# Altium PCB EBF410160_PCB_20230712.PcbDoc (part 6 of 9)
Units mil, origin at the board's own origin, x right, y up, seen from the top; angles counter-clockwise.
Board outline 5393.69 x 3858.26 mil, 6 copper layers (TOP, GND02, ART03, POW04, GND05, BOTTOM), stack 47.2 mil thick; 572 components, 434 nets, 2057 pads, 1177 vias.
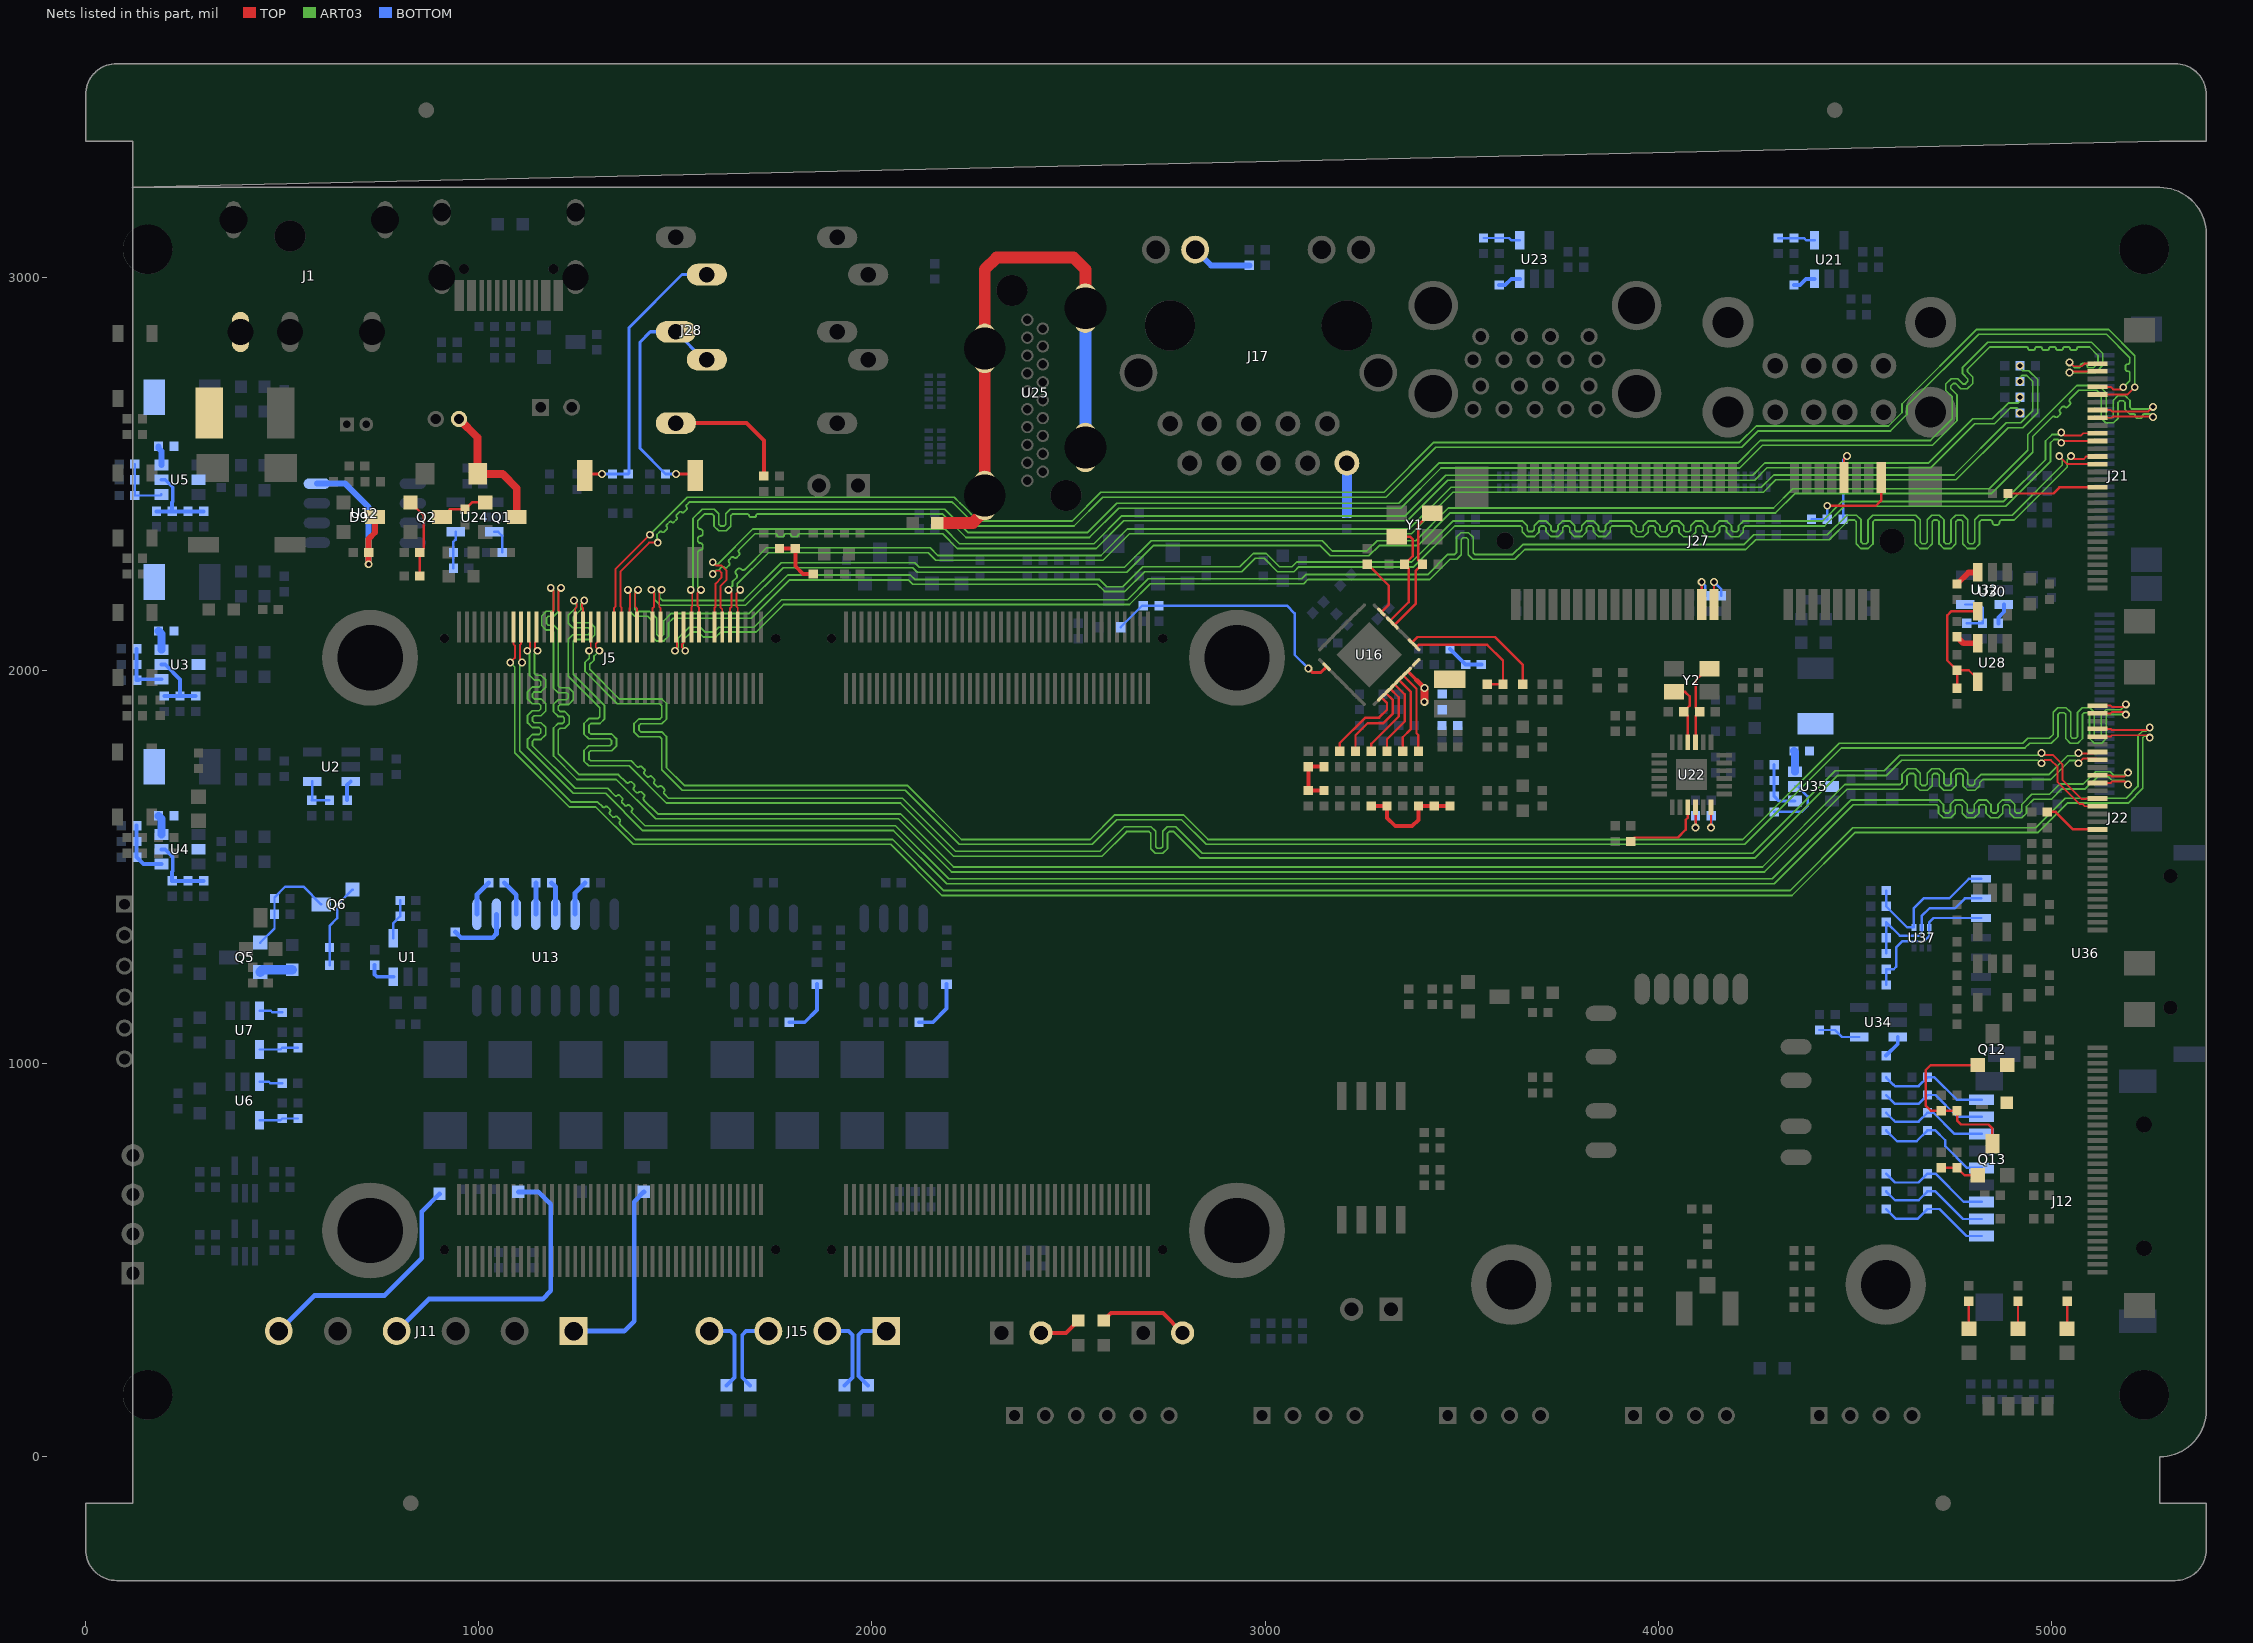
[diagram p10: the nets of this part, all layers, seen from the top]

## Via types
v1: diameter 20, hole 12, TOP to BOTTOM, 1177 vias

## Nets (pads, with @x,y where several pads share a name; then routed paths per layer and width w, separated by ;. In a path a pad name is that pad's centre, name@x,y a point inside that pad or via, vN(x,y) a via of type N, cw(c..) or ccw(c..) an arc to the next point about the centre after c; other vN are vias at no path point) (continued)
MIPI_CSI_RX_D2N: J5.69 R178.1 R180.1 | length 3734.7
  TOP w4.88: v1(1595,2275) 1603.56,2266.44 1617.58,2266.44 1630,2254.02 1630,2230.46 1615,2215.46 1615,2160 1619.28,2155.72 J5.69@1619.28,2110.98
  ART03 w4.44: v1(1595,2275) 1599.85,2270.16 1606.28,2270.15 1607.46,2270.15 1697.31,2360 2185,2360 2222.56,2322.44 2564.85,2322.44 2635.4,2392.99 3356.06,2392.99 3459.43,2496.36 4240.1,2496.36 4271.53,2527.79 4687.79,2527.79 4800,2640 4850,2640 4890,2680 4915,2680 4920,2685 v1(4920,2695)
MIPI_CSI_RX_D2P: J5.67 R176.1 R177.1 | length 3753
  TOP w4.88: v1(1595,2245) 1603.56,2253.56 1612.24,2253.56 1617.12,2248.68 1617.12,2235.79 1602.12,2220.79 1602.12,2162.12 1599.6,2159.6 J5.67@1599.6,2110.98
  ART03 w4.44: v1(1595,2245) 1595,2246.44 1603.56,2255 1609.9,2255 1617.09,2262.18 cw(c1620.64,2258.63) 1624.19,2262.18 ccw(c1627.75,2265.74) 1631.3,2262.18 1636.75,2267.63 ccw(c1633.2,2271.19) 1636.75,2274.74 cw(c1640.31,2278.3) 1636.75,2281.85 1642.2,2287.3 cw(c1645.76,2283.75) 1649.31,2287.3 ccw(c1652.87,2290.85) 1656.42,2287.3 1661.87,2292.75 ccw(c1658.32,2296.3) 1661.87,2299.86 cw(c1665.42,2303.41) 1661.87,2306.97 1702.46,2347.56 1754.84,2347.56 cw(c1754.84,2343.78) 1758.62,2343.78 ccw(c1762.4,2343.78) 1762.4,2340 1772.6,2340 ccw(c1772.6,2343.78) 1776.38,2343.78 cw(c1780.16,2343.78) 1780.16,2347.56 1790.36,2347.56 cw(c1790.36,2343.78) 1794.14,2343.78 ccw(c1797.92,2343.78) 1797.92,2340 1808.12,2340 ccw(c1808.12,2343.78) 1811.9,2343.78 cw(c1815.68,2343.78) 1815.68,2347.56 2179.85,2347.56 2217.41,2310 2570,2310 2640.55,2380.55 3361.21,2380.55 3464.58,2483.92 4245.25,2483.92 4276.68,2515.35 4692.94,2515.35 4805.15,2627.56 4855.15,2627.56 4895.15,2667.56 4912.44,2667.56 4920,2660 v1(4920,2655)
MIPI_CSI_RX_D3N: J5.73 R184.1 R185.1 | length 3768.8
  TOP w4.88: J5.73@1658.65,2110.98 1658.65,2159.1 1655.71,2162.04 1655.71,2195.71 v1(1665,2205)
  ART03 w4.44: v1(1665,2205) 1657.44,2212.56 1657.44,2220 1736.88,2299.44 2142.97,2299.44 2162.41,2280 2587.59,2280 2655.15,2347.56 3372.2,2347.56 3478.01,2453.37 4267.57,2453.37 4298.88,2484.68 4757.27,2484.68 4890.15,2617.56 4927.56,2617.56 4965,2655 4965,2740 4942.56,2762.44 4927,2762.44 4920,2769.44 v1(4920,2775)
MIPI_CSI_RX_D3P: J5.71 R182.1 R183.1 | length 3768.6
  TOP w4.88: v1(1635,2205) 1642.83,2197.17 1642.83,2162.13 1638.97,2158.27 J5.71@1638.97,2110.98
  ART03 w4.44: v1(1635,2205) 1645,2215 1645,2225.15 1654.88,2235.03 ccw(c1649.92,2239.99) 1654.88,2244.95 cw(c1659.84,2249.91) 1654.88,2254.87 1657.51,2257.51 cw(c1662.47,2252.55) 1667.44,2257.51 ccw(c1672.4,2262.47) 1677.36,2257.51 1731.73,2311.88 2148.12,2311.88 2167.56,2292.44 2582.44,2292.44 2650,2360 3367.05,2360 3472.86,2465.81 4262.42,2465.81 4293.73,2497.12 4752.12,2497.12 4885,2630 4922.41,2630 4952.56,2660.15 4952.56,2734.85 4937.41,2750 4925,2750 4920,2745 v1(4920,2735)
MIPI_DSI_TX0_CLKN: J5.53 J21.24 | length 4491.4
  TOP w4.88: J5.53@1461.8,2110.98 1461.8,2159.1 1458.86,2162.04 1458.86,2198.95 v1(1464.96,2205.05) ; J21.24@5117.47,2662.33 5150.54,2662.33 5153.95,2658.92 5246.74,2658.92 5250.74,2662.92 5250.82,2662.92 v1(5258.38,2670.48)
  ART03 w4.44: v1(1464.96,2205.05) 1459.96,2200.04 1459.96,2184.44 1466.3,2178.1 1673.1,2178.1 1768.8,2273.8 2108.8,2273.8 2120.15,2262.44 2642.44,2262.44 2710,2330 3145,2330 3171.22,2303.78 3258.78,2303.78 3285,2330 3382.91,2330 3466.03,2413.12 4293.12,2413.12 4342.26,2462.26 4842.26,2462.26 4940,2560 4940,2600 5064.85,2724.85 5120.15,2724.85 5139.36,2705.64 5139.36,2646.88 5143.81,2642.44 5152.69,2642.44 5157.12,2646.88 5157.12,2686.7 5168.85,2698.43 5188.04,2698.43 5199.77,2686.7 5199.77,2669.12 5204.2,2664.68 5252.58,2664.68 v1(5258.38,2670.48)
MIPI_DSI_TX0_CLKP: J5.51 J21.23 | length 4544.6
  TOP w4.88: v1(1438.96,2205.05) 1445.98,2198.02 1445.98,2162.13 1442.12,2158.27 J5.51@1442.12,2110.98 ; J21.23@5117.47,2642.64 5153.81,2642.64 5157.22,2646.04 5256.82,2646.04 v1(5258.38,2644.48)
  ART03 w4.44: v1(1438.96,2205.05) 1447.52,2196.49 1447.52,2179.29 1461.14,2165.66 1678.25,2165.66 1773.95,2261.36 2103.64,2261.36 2115,2250 2647.59,2250 2715.15,2317.56 3139.85,2317.56 3166.07,2291.34 3263.93,2291.34 3290.15,2317.56 3388.06,2317.56 3471.18,2400.68 4298.27,2400.68 4347.41,2449.82 4847.41,2449.82 4952.44,2554.85 4952.44,2594.85 5002.7,2645.1 cw(c5006.02,2641.78) 5009.35,2645.1 ccw(c5012.68,2648.43) 5016,2645.1 5021.91,2651.01 ccw(c5018.58,2654.34) 5021.91,2657.66 cw(c5025.23,2660.99) 5021.91,2664.31 5027.81,2670.22 cw(c5031.14,2666.89) 5034.47,2670.22 ccw(c5037.79,2673.55) 5041.12,2670.22 5047.03,2676.13 ccw(c5043.7,2679.45) 5047.03,2682.78 ; 5047.02,2682.78 cw(c5050.35,2686.11) 5047.02,2689.43 5070,2712.41 5115,2712.41 5126.93,2700.48 5126.93,2641.73 5138.65,2630 5157.84,2630 5169.56,2641.73 5169.56,2681.55 5174.01,2685.99 5182.89,2685.99 5187.32,2681.55 5187.32,2663.97 5199.05,2652.24 5208.49,2652.24 cw(c5208.49,2646.92) 5213.81,2646.92 ccw(c5219.13,2646.92) 5219.13,2641.6 5226.25,2641.6 ccw(c5226.25,2646.92) 5231.57,2646.92 cw(c5236.89,2646.92) 5236.89,2652.24 5250.62,2652.24 v1(5258.38,2644.48)
MIPI_DSI_TX0_D0N: J5.43 J21.27 | length 4526.5
  TOP w4.88: J5.43@1363.38,2110.98 1363.38,2159.1 1360.44,2162.04 1360.44,2252.22 1433.22,2325 v1(1455,2325) ; J21.27@5117.47,2721.38 5150.55,2721.38 5156.93,2715 5177.56,2715 v1(5182.7,2720.14)
  ART03 w4.44: v1(1455,2325) 1453.22,2326.78 1453.22,2345.63 1459.9,2352.3 cw(c1462.79,2349.42) 1465.68,2352.31 ccw(c1468.57,2355.19) 1471.45,2352.31 1478.24,2359.09 ccw(c1475.35,2361.97) 1478.23,2364.86 cw(c1481.12,2367.75) 1478.23,2370.64 1485.02,2377.42 cw(c1487.9,2374.53) 1490.79,2377.42 ccw(c1493.68,2380.31) 1496.57,2377.42 1503.35,2384.2 ccw(c1500.46,2387.09) 1503.35,2389.98 cw(c1506.24,2392.87) 1503.35,2395.76 1510.13,2402.54 cw(c1513.02,2399.65) 1515.91,2402.54 ccw(c1518.8,2405.43) 1521.69,2402.54 1528.47,2409.32 ccw(c1525.58,2412.21) 1528.47,2415.1 cw(c1531.36,2417.99) 1528.47,2420.88 1535.69,2428.1 2204.31,2428.1 2211.59,2420.82 2265,2367.41 2513.8,2367.41 2587.05,2440.66 3307.44,2440.66 3434.29,2567.51 4212.51,2567.51 4254.15,2609.15 4590.79,2609.15 4632.44,2650.8 4632.44,2672.44 4815,2855 5140,2855 5199.5,2795.5 5199.5,2784.51 cw(c5193.9,2784.51) 5193.9,2778.92 ccw(c5193.9,2773.32) 5188.31,2773.32 5188.31,2766.75 ccw(c5193.9,2766.75) 5193.9,2761.16 cw(c5193.9,2755.56) 5199.5,2755.56 5199.5,2736.94 v1(5182.7,2720.14)
MIPI_DSI_TX0_D0P: J5.41 J21.26 | length 4538.3
  TOP w4.88: J5.41@1343.69,2110.98 1343.69,2158.27 1347.56,2162.13 1347.56,2257.56 v1(1435,2345) ; J21.26@5117.47,2701.7 5193.36,2701.7 v1(5211.94,2720.28)
  ART03 w4.44: v1(1435,2345) 1530.54,2440.54 2209.46,2440.54 2224.03,2425.97 2227.68,2422.32 2270.15,2379.85 2508.65,2379.85 2581.9,2453.1 3302.29,2453.1 3429.14,2579.95 4207.36,2579.95 4249,2621.59 4585.64,2621.59 4620,2655.95 4620,2677.59 4809.85,2867.44 5145.15,2867.44 5211.94,2800.65 v1(5211.94,2720.28)
MIPI_DSI_TX0_D1N: J5.47 J21.21 | length 4560.8
  TOP w4.88: J5.47@1402.75,2110.98 1402.75,2157.25 1397.88,2162.12 1397.88,2197.88 v1(1405,2205) ; v1(5025,2605) 5032.33,2597.67 5075.52,2597.67 5081.12,2603.27 J21.21@5117.47,2603.27
  ART03 w4.44: v1(1405,2205) 1397.44,2197.44 1397.44,2154.44 1401.88,2150 1435,2150 1452.26,2132.74 1452.26,2091.88 1456.7,2087.44 1465.58,2087.44 1470.02,2091.88 1470.02,2125.71 1489.31,2145 1687.84,2145 1785.52,2242.68 2097.32,2242.68 2108.55,2231.45 2578.55,2231.45 2596.9,2213.1 2638.1,2213.1 2688.46,2263.46 2935.87,2263.46 2969.84,2297.43 3002.57,2297.43 3036.54,2263.46 3068.46,2263.46 3080.68,2275.68 3373.05,2275.68 3477.16,2379.79 3654.88,2379.79 3666.61,2368.06 3666.61,2357.54 3671.05,2353.1 3679.93,2353.1 3684.37,2357.54 3684.37,2368.06 3696.09,2379.79 3715.28,2379.79 3727.01,2368.06 3727.01,2357.54 3731.45,2353.1 3740.33,2353.1 3744.77,2357.54 3744.77,2368.06 3756.49,2379.79 3775.68,2379.79 3787.41,2368.06 3787.41,2357.54 3791.85,2353.1 3800.73,2353.1 3805.17,2357.54 3805.17,2368.06 3816.89,2379.79 3836.08,2379.79 3847.81,2368.06 3847.81,2357.54 3852.25,2353.1 3861.13,2353.1 3865.57,2357.54 3865.57,2368.06 3877.29,2379.79 3932.37,2379.79 3944.1,2368.06 3944.1,2356.88 3948.54,2352.44 3957.42,2352.44 3961.86,2356.88 3961.86,2368.06 3973.59,2379.79 3992.77,2379.79 4004.5,2368.06 4004.5,2356.88 4008.94,2352.44 4017.82,2352.44 4022.26,2356.88 4022.26,2368.06 4033.99,2379.79 4053.17,2379.79 4064.9,2368.06 4064.9,2356.88 4069.34,2352.44 4078.22,2352.44 4082.66,2356.88 4082.66,2368.06 4094.39,2379.79 4113.57,2379.79 4125.3,2368.06 4125.3,2356.88 4129.74,2352.44 4138.62,2352.44 4143.06,2356.88 4143.06,2368.06 4154.79,2379.79 4174.53,2379.79 4186.26,2368.06 4186.26,2356.88 4190.7,2352.44 4199.58,2352.44 4204.02,2356.88 4204.02,2368.06 4215.75,2379.79 4417.74,2379.79 4467.81,2429.86 4878.67,2429.86 4985,2536.19 4985,2583.47 5001.41,2599.88 5019.88,2599.88 v1(5025,2605)
MIPI_DSI_TX0_D1P: J5.45 J21.20 | length 4577
  TOP w4.88: v1(1379,2205) 1385,2199 1385,2160 1383.06,2158.07 J5.45@1383.06,2110.98 ; v1(5025,2579) 5029.59,2583.59 J21.20@5117.47,2583.59
  ART03 w4.44: v1(1379,2205) 1385,2199 1385,2149.29 1396.73,2137.56 1429.85,2137.56 1439.82,2127.59 1439.82,2086.73 1451.55,2075 1470.73,2075 1482.46,2086.73 1482.46,2120.56 1494.46,2132.56 1692.99,2132.56 1790.67,2230.24 2092.17,2230.24 2103.4,2219.01 2573.4,2219.01 2591.75,2200.66 2643.25,2200.66 2693.61,2251.02 2941.02,2251.02 2974.99,2284.99 2997.42,2284.99 3031.39,2251.02 3073.61,2251.02 3085.83,2263.24 3378.2,2263.24 3482.31,2367.35 3649.73,2367.35 3654.17,2362.91 3654.17,2352.39 3665.89,2340.66 3685.08,2340.66 3696.81,2352.39 3696.81,2362.91 3701.25,2367.35 3710.13,2367.35 3714.57,2362.91 3714.57,2352.39 3726.29,2340.66 3745.48,2340.66 3757.21,2352.39 3757.21,2362.91 3761.65,2367.35 3770.53,2367.35 3774.97,2362.91 3774.97,2352.39 3786.69,2340.66 3805.88,2340.66 3817.61,2352.39 3817.61,2362.91 3822.05,2367.35 3830.93,2367.35 3835.37,2362.91 3835.37,2352.39 3847.09,2340.66 3866.28,2340.66 3878.01,2352.39 3878.01,2362.91 3882.45,2367.35 3927.22,2367.35 3931.66,2362.91 3931.66,2351.73 3943.39,2340 3962.57,2340 3974.3,2351.73 3974.3,2362.91 3978.74,2367.35 3987.62,2367.35 3992.06,2362.91 3992.06,2351.73 4003.79,2340 4022.97,2340 4034.7,2351.73 4034.7,2362.91 4039.14,2367.35 4048.02,2367.35 4052.46,2362.91 4052.46,2351.73 4064.19,2340 4083.37,2340 4095.1,2351.73 4095.1,2362.91 4099.54,2367.35 4108.42,2367.35 4112.86,2362.91 4112.86,2351.73 4124.59,2340 4143.77,2340 4155.5,2351.73 4155.5,2362.91 4159.94,2367.35 4169.38,2367.35 4173.82,2362.91 4173.82,2351.73 4185.55,2340 4204.73,2340 4216.46,2351.73 4216.46,2362.91 4220.9,2367.35 4422.89,2367.35 4472.96,2417.42 4883.82,2417.42 4997.44,2531.04 4997.44,2578.31 5006.57,2587.44 5016.56,2587.44 v1(5025,2579)
MIPI_DSI_TX0_D2N: J5.59 J21.18 | length 4523.9
  TOP w4.88: J5.59@1520.86,2110.98 1520.86,2070.86 1516.99,2067 1516.99,2058.01 v1(1525,2050) ; v1(5050,2545) 5057.59,2537.41 5082.41,2537.41 5089.22,2544.22 J21.18@5117.47,2544.22
  ART03 w4.44: v1(1525,2050) 1520,2055 1520,2077.41 1540.15,2097.56 1558.19,2097.56 1570.75,2085 1602.59,2085 1615.15,2097.56 1705.15,2097.56 1775.15,2167.56 2655.15,2167.56 2708.25,2220.66 3098.25,2220.66 3108.81,2231.22 3418.81,2231.22 3470.15,2282.56 3487.26,2282.56 3498.99,2294.29 3498.99,2333.12 3503.43,2337.56 3512.31,2337.56 3516.75,2333.12 3516.75,2294.29 3528.48,2282.56 3635.15,2282.56 3660.15,2307.56 4222.56,2307.56 4247.56,2332.56 4435.15,2332.56 4485.15,2382.56 4499.02,2382.56 4503.46,2378.12 4503.46,2321.73 4515.19,2310 4534.37,2310 4546.1,2321.73 4546.1,2378.12 4550.54,2382.56 4649.51,2382.56 4653.95,2378.12 4653.95,2321.73 4665.68,2310 4684.86,2310 4696.59,2321.73 4696.59,2378.12 4701.03,2382.56 4709.91,2382.56 4714.35,2378.12 4714.35,2321.73 4726.08,2310 4745.27,2310 4756.99,2321.73 4756.99,2378.12 4761.43,2382.56 4770.31,2382.56 4774.75,2378.12 4774.75,2321.73 4786.48,2310 4805.66,2310 4817.39,2321.73 4817.39,2378.12 4821.83,2382.56 4843.95,2382.56 cw(c4843.95,2376.28) 4850.23,2376.28 ccw(c4856.51,2376.28) 4856.51,2370 4861.71,2370 ccw(c4861.71,2376.28) 4867.99,2376.28 cw(c4874.27,2376.28) 4874.27,2382.56 4905.15,2382.56 5040,2517.41 5040,2536.01 5048.99,2545 v1(5050,2545)
MIPI_DSI_TX0_D2P: J5.57 J21.17 | length 4540.7
  TOP w4.88: v1(1499,2050) 1499.23,2050 1504.12,2054.88 1504.12,2070.89 1501.17,2073.83 J5.57@1501.17,2110.98 ; v1(5020,2545) 5040.47,2524.53 J21.17@5117.47,2524.53
  ART03 w4.44: v1(1499,2050) 1499.23,2050 1507.56,2058.33 1507.56,2082.56 1535,2110 1563.34,2110 1575.9,2097.44 1597.44,2097.44 1610,2110 1700,2110 1770,2180 2650,2180 2703.1,2233.1 3093.1,2233.1 3103.66,2243.66 3413.66,2243.66 3465,2295 3482.11,2295 3486.55,2299.44 3486.55,2338.27 3498.28,2350 3517.46,2350 3529.19,2338.27 3529.19,2299.44 3533.63,2295 3630,2295 3655,2320 4217.41,2320 4242.41,2345 4430,2345 4480,2395 4504.17,2395 4515.9,2383.27 4515.9,2326.88 4520.34,2322.44 4529.22,2322.44 4533.66,2326.88 4533.66,2383.27 4545.39,2395 4654.66,2395 4666.39,2383.27 4666.39,2326.88 4670.83,2322.44 4679.71,2322.44 4684.15,2326.88 4684.15,2383.27 4695.88,2395 4715.06,2395 4726.79,2383.27 4726.79,2326.88 4731.23,2322.44 4740.11,2322.44 4744.55,2326.88 4744.55,2383.27 4756.28,2395 4775.47,2395 4787.19,2383.27 4787.19,2326.88 4791.63,2322.44 4800.51,2322.44 4804.95,2326.88 4804.95,2383.27 4816.68,2395 4900,2395 5027.56,2522.56 5027.56,2537.44 v1(5020,2545)
MIPI_DSI_TX0_D3N: J5.63 J21.30 | length 4537.1
  TOP w4.88: J5.63@1560.23,2110.98 1560.23,2159.77 1555.78,2164.22 1555.78,2195.78 v1(1565,2205) ; v1(5046.24,2783.6) 5056.21,2773.62 5077.57,2773.62 5084.39,2780.44 J21.30@5117.47,2780.44
  ART03 w4.44: v1(1565,2205) 1557.05,2212.95 1557.05,2299.59 cw(c1563.6,2299.59) 1563.6,2306.13 ccw(c1563.6,2311.97) 1569.43,2311.97 1569.43,2318.06 ccw(c1563.6,2318.06) 1563.6,2323.89 cw(c1563.6,2330.44) 1557.05,2330.44 1557.05,2335.11 cw(c1563.6,2335.11) 1563.6,2341.65 ccw(c1563.6,2347.49) 1569.43,2347.49 1569.43,2353.58 ccw(c1563.6,2353.58) 1563.6,2359.41 cw(c1563.6,2365.96) 1557.05,2365.96 1557.05,2381.17 1573.44,2397.56 1593.63,2397.56 1598.07,2393.12 1598.07,2366.73 1609.8,2355 1628.98,2355 1640.71,2366.73 1640.71,2393.12 1645.15,2397.56 1683.71,2397.56 cw(c1683.71,2393.78) 1687.49,2393.78 ccw(c1691.27,2393.78) 1691.27,2390 1701.47,2390 ccw(c1701.47,2393.78) 1705.25,2393.78 cw(c1709.03,2393.78) 1709.03,2397.56 2179.85,2397.56 2239.31,2338.1 2553.1,2338.1 2627.56,2412.56 3345.02,2412.56 3447.29,2514.83 4207.42,2514.83 4265.24,2572.65 4697.65,2572.65 4759.96,2634.96 4759.96,2701 4743.79,2717.16 4743.79,2723.44 4750.08,2729.72 4756.36,2729.72 4769.76,2716.32 4786.34,2716.32 4799.91,2729.89 4799.91,2746.47 4786.51,2759.88 4786.51,2766.15 4842.91,2822.56 4936.9,2822.56 cw(c4936.9,2818.78) 4940.68,2818.78 ccw(c4944.46,2818.78) 4944.46,2815 4954.66,2815 ccw(c4954.66,2818.78) 4958.44,2818.78 cw(c4962.22,2818.78) 4962.22,2822.56 4972.42,2822.56 cw(c4972.42,2818.78) 4976.2,2818.78 ccw(c4979.98,2818.78) 4979.98,2815 4990.18,2815 ccw(c4990.18,2818.78) 4993.96,2818.78 cw(c4997.74,2818.78) 4997.74,2822.56 5007.94,2822.56 cw(c5007.94,2818.78) 5011.72,2818.78 ccw(c5015.5,2818.78) 5015.5,2815 5025.7,2815 ccw(c5025.7,2818.78) 5029.48,2818.78 cw(c5033.26,2818.78) 5033.26,2822.56 5043.46,2822.56 cw(c5043.46,2818.78) 5047.24,2818.78 ccw(c5051.02,2818.78) 5051.02,2815 5061.22,2815 ccw(c5061.22,2818.78) 5065,2818.78 cw(c5068.78,2818.78) 5068.78,2822.56 5096.78,2822.56 5118.24,2801.1 5118.24,2781.29 5106.99,2770.04 5095.05,2770.04 cw(c5095.05,2774.06) 5091.02,2774.06 ; v1(5046.24,2783.6) 5059.8,2770.04 5069.24,2770.04 ccw(c5069.24,2774.06) 5073.26,2774.06 ; 5073.26,2774.08 cw(c5079.63,2774.08) 5079.63,2780.45 5084.66,2780.45 cw(c5084.66,2774.08) 5091.02,2774.08
MIPI_DSI_TX0_D3P: J5.61 J21.29 | length 4500.3
  TOP w4.88: v1(1539,2205) 1542.9,2201.1 1542.9,2162.9 1540.54,2160.54 J5.61@1540.54,2110.98 ; v1(5046.24,2757.6) 5049.38,2760.74 J21.29@5117.47,2760.74
  ART03 w4.44: v1(1539,2205) 1544.61,2210.61 1544.61,2386.32 1568.29,2410 1598.79,2410 1610.51,2398.27 1610.51,2371.88 1614.95,2367.44 1623.83,2367.44 1628.27,2371.88 1628.27,2398.27 1640,2410 2185,2410 2244.46,2350.54 2547.95,2350.54 2622.41,2425 3339.87,2425 3442.14,2527.27 4202.27,2527.27 4260.09,2585.09 4692.5,2585.09 4747.52,2640.11 4747.52,2695.84 4731.35,2712.01 4731.35,2728.59 4744.93,2742.16 4761.51,2742.16 4774.91,2728.76 4781.19,2728.76 4787.47,2735.04 4787.47,2741.32 4774.07,2754.72 4774.07,2771.31 4837.76,2835 5101.93,2835 5130.68,2806.25 5130.68,2776.14 5112.14,2757.6 v1(5046.24,2757.6)
MIPI_DSI_TX1_CLKN: J5.27 J22.24 | length 5042.5
  TOP w4.88: J5.27@1205.9,2110.98 1205.9,2149.1 1202.88,2152.12 1202.88,2203.87 v1(1209.06,2210.05) ; v1(5069,1790) 5070.02,1788.98 5114.13,1788.98 J22.24@5117.47,1792.33
  ART03 w4.44: v1(1209.06,2210.05) 1202.28,2203.26 1202.28,2149.47 1190.55,2137.74 1176.88,2137.74 1172.44,2133.3 1172.44,2119.43 1176.88,2114.99 1190.55,2114.99 1202.28,2103.26 1202.28,1960.26 1206.72,1955.82 1228.27,1955.82 1240,1944.09 1240,1924.91 1228.27,1913.18 1206.72,1913.18 1202.28,1908.74 1202.28,1899.86 1206.72,1895.42 1218.27,1895.42 1230,1883.69 1230,1864.51 1218.27,1852.78 1206.72,1852.78 1202.28,1848.34 1202.28,1787.72 1255,1735 1355,1735 1374.73,1715.27 ccw(c1378.48,1719.02) 1382.23,1715.27 cw(c1385.98,1711.52) 1389.73,1715.27 1394.79,1710.21 cw(c1391.04,1706.46) 1394.79,1702.71 ccw(c1398.54,1698.96) 1394.79,1695.21 1399.85,1690.15 ccw(c1403.6,1693.9) 1407.35,1690.15 cw(c1411.1,1686.4) 1414.85,1690.15 1419.91,1685.09 cw(c1416.16,1681.34) 1419.91,1677.59 ccw(c1423.66,1673.84) 1419.91,1670.09 1455,1635 2072.59,1635 2207.59,1500 4265,1500 4475,1710 4615,1710 4620,1715 4620,1736.13 4633.87,1750 4654.75,1750 4666.47,1738.27 4666.47,1711.88 4670.91,1707.44 4679.79,1707.44 4684.23,1711.88 4684.23,1738.27 4695.96,1750 4715.15,1750 4726.87,1738.27 4726.87,1711.88 4731.31,1707.44 4740.19,1707.44 4744.63,1711.88 4744.63,1738.27 4756.36,1750 4775.55,1750 4787.27,1738.27 4787.27,1711.88 4791.71,1707.44 4800.59,1707.44 4805.03,1711.88 4805.03,1720.03 4820,1735 4992.94,1735 5040.94,1783 5062,1783 v1(5069,1790)
MIPI_DSI_TX1_CLKP: J5.25 J22.23 | length 5044
  TOP w4.88: v1(1183.06,2210.05) 1190,2203.1 1190,2151.78 1186.21,2148 J5.25@1186.21,2110.98 ; v1(5069,1764) 5069.08,1764 5081.18,1776.11 5114,1776.11 J22.23@5117.47,1772.64
  ART03 w4.44: v1(1183.06,2210.05) 1189.84,2203.26 1189.84,2154.62 1185.4,2150.18 1171.73,2150.18 1160,2138.46 1160,2114.27 1171.73,2102.55 1185.4,2102.55 1189.84,2098.11 1189.84,1955.11 1201.56,1943.38 1223.12,1943.38 1227.56,1938.94 1227.56,1930.06 1223.12,1925.62 1201.56,1925.62 1189.84,1913.89 1189.84,1894.71 1201.56,1882.98 1213.12,1882.98 1217.56,1878.54 1217.56,1869.66 1213.12,1865.22 1201.56,1865.22 1189.84,1853.49 1189.84,1782.57 1249.85,1722.56 1349.85,1722.56 1449.85,1622.56 2067.44,1622.56 2202.44,1487.56 4270.15,1487.56 4480.15,1697.56 4620.15,1697.56 4632.44,1709.85 4632.44,1730.97 4639.03,1737.56 4649.59,1737.56 4654.03,1733.12 4654.03,1706.73 4665.76,1695 4684.95,1695 4696.67,1706.73 4696.67,1733.12 4701.11,1737.56 4709.99,1737.56 4714.43,1733.12 4714.43,1706.73 4726.16,1695 4745.35,1695 4757.07,1706.73 4757.07,1733.12 4761.51,1737.56 4770.39,1737.56 4774.83,1733.12 4774.83,1706.73 4786.56,1695 4805.75,1695 4817.47,1706.73 4817.47,1714.88 4825.15,1722.56 4998.09,1722.56 5046.09,1770.56 5062.44,1770.56 v1(5069,1764)
MIPI_DSI_TX1_D0N: J5.17 J22.27 | length 5019.9
  TOP w4.88: J5.17@1107.47,2110.98 1107.47,2067.47 1104.65,2064.65 1104.65,2025.35 v1(1110,2020) ; J22.27@5117.47,1851.38 5150.55,1851.38 5153.95,1847.98 5245.12,1847.98 5250,1852.86 v1(5250,1855)
  ART03 w4.44: v1(1110,2020) 1103.85,2013.85 1103.85,1796.15 1235,1665 1302.59,1665 1314.81,1652.78 ccw(c1317.91,1655.88) 1321.01,1652.78 cw(c1324.12,1649.68) 1327.22,1652.78 1333.58,1646.42 cw(c1330.47,1643.32) 1333.58,1640.22 ; 1333.57,1640.22 ccw(c1336.68,1637.12) 1333.57,1634.02 1339.93,1627.66 ccw(c1343.03,1630.76) 1346.13,1627.66 cw(c1349.23,1624.56) 1352.34,1627.66 1358.69,1621.31 cw(c1355.59,1618.2) 1358.69,1615.1 ccw(c1361.79,1612) 1358.69,1608.9 1397.59,1570 2052.59,1570 2182.59,1440 4335,1440 4495,1600 4960,1600 5035,1675 5190,1675 5220,1705 5220,1833.8 5231.73,1845.53 5240.53,1845.53 v1(5250,1855)
MIPI_DSI_TX1_D0P: J5.15 J22.26 | length 5021.9
  TOP w4.88: v1(1080,2020) 1091.77,2031.77 1091.77,2063.23 1087.79,2067.21 J5.15@1087.79,2110.98 ; J22.26@5117.47,1831.7 5150.55,1831.7 5153.95,1835.1 5243.9,1835.1 v1(5250,1829)
  ART03 w4.44: v1(1080,2020) 1091.41,2008.59 1091.41,1791 1229.85,1652.56 1297.44,1652.56 1392.44,1557.56 2047.44,1557.56 2177.44,1427.56 4340.15,1427.56 4500.15,1587.56 4965.15,1587.56 5040.15,1662.56 5195.15,1662.56 5232.44,1699.85 5232.44,1828.65 5236.88,1833.09 5245.91,1833.09 v1(5250,1829)
MIPI_DSI_TX1_D1N: J5.21 J22.21 | length 5061.3
  TOP w4.88: J5.21@1146.84,2110.98 1146.84,2074.84 1143,2071 1143,2056.09 v1(1149.09,2050) ; J22.21@5117.47,1733.27 5150.55,1733.27 5153.95,1729.87 5184.87,1729.87 v1(5195,1740)
  ART03 w4.44: v1(1149.09,2050) 1141.44,2042.35 1141.44,1992.41 1145.88,1987.97 1158.27,1987.97 1170,1976.24 1170,1957.06 1158.27,1945.33 1140.88,1945.33 1136.44,1940.89 1136.44,1932.01 1140.88,1927.57 1158.27,1927.57 1170,1915.84 1170,1896.65 1158.27,1884.93 1140.88,1884.93 1136.44,1880.49 1136.44,1871.61 1140.88,1867.17 1158.27,1867.17 1170,1855.44 1170,1836.26 1158.27,1824.53 1140.88,1824.53 1136.44,1820.09 1136.44,1808.56 1245,1700 1327.59,1700 1345.8,1681.79 ccw(c1348.9,1684.89) 1352,1681.79 cw(c1355.1,1678.69) 1358.2,1681.79 1364.56,1675.44 cw(c1361.46,1672.34) 1364.56,1669.24 ccw(c1367.66,1666.13) 1364.56,1663.03 1370.92,1656.67 ccw(c1374.02,1659.78) 1377.12,1656.68 cw(c1380.22,1653.58) 1383.32,1656.68 1389.68,1650.32 cw(c1386.58,1647.22) 1389.68,1644.12 ccw(c1392.78,1641.02) 1389.68,1637.91 1422.59,1605 2060,1605 2195,1470 4290,1470 4490.66,1670.66 4713.58,1670.66 4725.31,1658.93 4725.31,1641.88 4729.74,1637.44 4738.62,1637.44 4743.06,1641.88 4743.06,1658.93 4754.79,1670.66 4773.98,1670.66 4785.7,1658.93 4785.7,1641.88 4790.15,1637.44 4799.02,1637.44 4803.47,1641.88 4803.47,1658.93 4815.19,1670.66 4834.38,1670.66 4846.1,1658.93 4846.1,1641.88 4850.55,1637.44 4859.43,1637.44 4863.86,1641.88 4863.86,1658.93 4875.59,1670.66 4894.78,1670.66 4906.51,1658.93 4906.51,1641.88 4910.94,1637.44 4919.82,1637.44 4924.27,1641.88 4924.27,1658.93 4950.33,1685 4995,1685 5021,1711 5081,1711 5112.44,1742.44 5150.15,1742.44 5160.15,1732.44 5187.44,1732.44 v1(5195,1740)
MIPI_DSI_TX1_D1P: J5.19 J22.20 | length 5060.9
  TOP w4.88: v1(1123.09,2050) 1130.12,2057.03 1130.12,2070.88 1127.16,2073.84 J5.19@1127.16,2110.98 ; J22.20@5117.47,1713.59 5150.55,1713.59 5153.95,1716.99 5188.01,1716.99 v1(5195,1710)
  ART03 w4.44: v1(1123.09,2050) 1129,2044.09 1129,1987.26 1140.73,1975.53 1153.12,1975.53 1157.56,1971.09 1157.56,1962.21 1153.12,1957.77 1135.73,1957.77 1124,1946.04 1124,1926.86 1135.73,1915.13 1153.12,1915.13 1157.56,1910.69 1157.56,1901.81 1153.12,1897.37 1135.73,1897.37 1124,1885.64 1124,1866.45 1135.73,1854.73 1153.12,1854.73 1157.56,1850.29 1157.56,1841.41 1153.12,1836.97 1135.73,1836.97 1124,1825.24 1124,1803.41 1239.85,1687.56 1322.44,1687.56 1417.44,1592.56 2054.85,1592.56 2189.85,1457.56 4295.15,1457.56 4495.81,1658.22 4708.43,1658.22 4712.86,1653.78 4712.86,1636.73 4724.59,1625 4743.78,1625 4755.51,1636.73 4755.51,1653.78 4759.94,1658.22 4768.82,1658.22 4773.27,1653.78 4773.27,1636.73 4784.99,1625 4804.18,1625 4815.9,1636.73 4815.9,1653.78 4820.35,1658.22 4829.23,1658.22 4833.66,1653.78 4833.66,1636.73 4845.39,1625 4864.58,1625 4876.31,1636.73 4876.31,1653.78 4880.74,1658.22 4889.62,1658.22 4894.06,1653.78 4894.06,1636.73 4905.79,1625 4924.98,1625 4936.7,1636.73 4936.7,1653.78 4955.48,1672.56 5000.15,1672.56 5026.15,1698.56 5086.15,1698.56 5117.59,1730 5145,1730 5155,1720 5185,1720 v1(5195,1710)
MIPI_DSI_TX1_D2N: J5.33 J22.18 | length 5048.7
  TOP w4.88: J5.33@1264.95,2110.98 1264.95,2159.1 1262.01,2162.04 1262.01,2171.95 v1(1268.11,2178.05) ; v1(4975,1790) 4980.19,1784.81 5004.11,1784.81 5027.88,1761.04 5027.88,1722.12 5077.36,1672.64 5087.64,1672.64 5089.22,1674.22 J22.18@5117.47,1674.22
  ART03 w4.44: v1(1268.11,2178.05) 1260,2169.93 1260,2155 1240,2135 1240,2125.56 1244.44,2121.12 1283.27,2121.12 1295,2109.39 1295,2090.21 1283.27,2078.48 1244.44,2078.48 1240,2074.04 1240,1990 1319.85,1910.15 1319.85,1876.73 1308.13,1865 1285.15,1865 1280,1859.85 1280,1842.76 1284.44,1838.32 1338.27,1838.32 1350,1826.6 1350,1807.41 1338.27,1795.68 1284.44,1795.68 1280,1791.24 1280,1774.44 1284.44,1770 1387.59,1770 1402.45,1755.15 ccw(c1405.55,1758.25) 1408.65,1755.15 cw(c1411.75,1752.05) 1414.85,1755.15 1421.21,1748.79 cw(c1418.11,1745.69) 1421.21,1742.59 ccw(c1424.31,1739.49) 1421.21,1736.39 1427.57,1730.03 ccw(c1430.67,1733.13) 1433.77,1730.03 cw(c1436.87,1726.93) 1439.97,1730.03 1446.33,1723.67 cw(c1443.23,1720.57) 1446.33,1717.47 ccw(c1449.43,1714.37) 1446.33,1711.27 1452.68,1704.91 ccw(c1455.78,1708.01) 1458.88,1704.91 cw(c1461.99,1701.81) 1465.09,1704.91 1471.44,1698.55 cw(c1468.34,1695.45) 1471.44,1692.35 ccw(c1474.55,1689.25) 1471.44,1686.15 1482.59,1675 2077.59,1675 2212.59,1540 2580,1540 2642.44,1602.44 2709.88,1602.44 2721.6,1590.71 2721.6,1551.88 2726.04,1547.44 2734.92,1547.44 2739.36,1551.88 2739.36,1590.71 2751.09,1602.44 2772.56,1602.44 2840,1535 4240,1535 4450,1745 4575,1745 4614.22,1784.22 4969.78,1784.22 4975,1789.44 v1(4975,1790)
MIPI_DSI_TX1_D2P: J5.31 J22.17 | length 5042.1
  TOP w4.88: v1(1242.11,2178.05) 1249.13,2171.02 1249.13,2162.13 1245.27,2158.27 J5.31@1245.27,2110.98 ; v1(4975,1764) 4982.93,1771.93 4998.77,1771.93 5015,1755.7 5015,1716.78 5072.02,1659.76 5079.98,1659.76 5085.21,1654.53 J22.17@5117.47,1654.53
  ART03 w4.44: v1(1242.11,2178.05) 1247.56,2172.6 1247.56,2160.15 1227.56,2140.15 1227.56,2120.41 1239.29,2108.68 1278.12,2108.68 1282.56,2104.24 1282.56,2095.36 1278.12,2090.92 1239.29,2090.92 1227.56,2079.19 1227.56,1984.85 1307.41,1904.99 1307.41,1881.88 1302.97,1877.44 1280,1877.44 1267.56,1865 1267.56,1837.61 1279.29,1825.88 1333.12,1825.88 1337.56,1821.44 1337.56,1812.56 1333.12,1808.12 1279.29,1808.12 1267.56,1796.4 1267.56,1769.29 1279.29,1757.56 1382.44,1757.56 1477.44,1662.56 2072.44,1662.56 2207.44,1527.56 2585.15,1527.56 2647.59,1590 2704.72,1590 2709.16,1585.56 2709.16,1546.73 2720.89,1535 2740.07,1535 2751.8,1546.73 2751.8,1585.56 2756.24,1590 2767.41,1590 2834.85,1522.56 4245.15,1522.56 4455.15,1732.56 4580.15,1732.56 4619.37,1771.78 4965.2,1771.78 4967.2,1769.78 4967.78,1769.78 4973.56,1764 v1(4975,1764)
MIPI_DSI_TX1_D3N: J5.37 J22.30 | length 5000.3
  TOP w4.88: J5.37@1304.32,2110.98 1304.32,2074.32 1297.52,2067.52 1297.52,2059.14 1302.76,2053.9 1302.76,2053.82 v1(1306.57,2050) ; J22.30@5117.47,1910.44 5150.54,1910.44 5153.95,1907.03 5182.85,1907.03 v1(5189.41,1913.59)
  ART03 w4.44: v1(1306.57,2050) 1293.01,2036.44 1293.01,2025.95 1282.44,2015.38 1282.44,2002.56 1357.56,1927.44 1465.71,1927.44 1477.44,1915.71 1477.44,1875.85 1465.71,1864.13 1411.88,1864.13 1407.44,1859.69 1407.44,1847.81 1411.59,1843.66 1465.42,1843.66 1477.44,1831.64 1477.44,1752.56 1522.56,1707.44 2090.15,1707.44 2227.59,1570 2555,1570 2617.44,1632.44 2792.56,1632.44 2855,1570 4215,1570 4460,1815 4927.41,1815 4939.85,1827.44 4994.85,1827.44 5004.55,1837.15 5004.55,1893.27 5016.28,1905 5037.15,1905 5048.88,1893.27 5048.88,1831.88 5053.32,1827.44 5062.2,1827.44 5066.64,1831.88 5066.64,1893.27 5078.37,1905 5097.55,1905 5109.28,1893.27 5109.28,1831.88 5113.72,1827.44 5122.6,1827.44 5127.04,1831.88 5127.04,1888.3 5138.77,1900.03 5176.08,1900.03 5189.41,1913.36 v1(5189.41,1913.59)
MIPI_DSI_TX1_D3P: J5.35 J22.29 | length 5004.7
  TOP w4.88: v1(1280.57,2050) 1284.64,2054.06 J5.35@1284.64,2110.98 ; J22.29@5117.47,1890.74 5150.55,1890.74 5153.95,1894.15 5182.85,1894.15 v1(5189.41,1887.59)
  ART03 w4.44: v1(1280.57,2050) 1280.57,2031.11 1270,2020.53 1270,1997.41 1352.41,1915 1460.56,1915 1465,1910.56 1465,1881.01 1460.56,1876.57 1406.73,1876.57 1395,1864.84 1395,1842.65 1406.43,1831.22 1460.27,1831.22 1465,1826.49 1465,1747.41 1517.41,1695 2085,1695 2222.44,1557.56 2560.15,1557.56 2622.59,1620 2787.41,1620 2849.85,1557.56 4220.15,1557.56 4465.15,1802.56 4932.56,1802.56 4945,1815 5000,1815 5016.99,1831.99 5016.99,1888.12 5021.43,1892.56 5032,1892.56 5036.44,1888.12 5036.44,1826.73 5048.17,1815 5067.35,1815 5079.08,1826.73 5079.08,1888.12 5083.52,1892.56 5092.4,1892.56 5096.84,1888.12 5096.84,1826.73 5108.57,1815 5127.75,1815 5139.48,1826.73 5139.48,1883.15 5143.92,1887.59 v1(5189.41,1887.59)
N02088: F1.1 J1.4
N03633: C7.1 U3.6 | length 50.7
  BOTTOM w20: C7.1@185.32,2100 192.76,2092.56 U3.6@192.76,2052.4
N03641: C7.2 L1.1 U3.2
N03801: C8.2 R4.2 R6.1 U3.4 | length 144.2
  BOTTOM w10: R4.2@129.68,2055 C8.2@129.68,2015 R6.1@129.68,1975 134.68,1975 137.28,1977.6 U3.4@192.76,1977.6
N28501: C28.1 U5.6 | length 50.7
  BOTTOM w15: C28.1@185.32,2570 185.32,2565 192.76,2557.56 U5.6@192.76,2522.4
N28533: C28.2 L3.1 U5.2
N15118698: C4.1 R1.2 U1.4 | length 103.1
  BOTTOM w6.16: U1.4@782.6,1319.21 782.6,1357.28 C4.1@800.32,1375 R1.2@800.32,1415
N15119063: R2.1 U1.3 | length 73.5
  BOTTOM w10: R2.1@735,1250.32 735,1226.95 741.16,1220.79 U1.3@782.6,1220.79
N15122947: C9.1 R3.2 U2.4 | length 93.2
  BOTTOM w6.16: U2.4@575.79,1717.6 575.79,1670.47 C9.1@575,1669.68 R3.2@620,1669.68
N15123057: R5.1 U2.3 | length 51.7
  BOTTOM w10: R5.1@665,1669.68 665,1708.38 U2.3@674.21,1717.6
N15599533: R96.2 U16.25 | length 199.5
  TOP w6.16: R96.2@3310,1794.68 3310,1825 3355,1870 3355,1938.87 U16.25@3329.03,1964.84
N15599537: R97.2 U16.24 | length 197.2
  TOP w6.16: R97.2@3270,1794.68 3270,1813.02 3340,1883.02 3340,1931.6 U16.24@3317.9,1953.7
N15599541: R99.2 U16.23 | length 218.2
  TOP w6.16: R99.2@3230,1794.68 3230,1835 3261.08,1866.08 3301.08,1866.08 3325,1890 3325,1924.32 U16.23@3306.76,1942.56
N15599545: R100.2 U16.22 | length 212.9
  TOP w6.16: R100.2@3190,1794.68 3190,1815 3255,1880 3290,1880 3310,1900 3310,1917.05 U16.22@3295.63,1931.43
N15599549: R101.2 U16.27 | length 208.5
  TOP w6.16: U16.27@3351.3,1987.1 3385,1953.4 3385,1840 3390,1835 R101.2@3390,1794.68
N15599553: R102.2 U16.26 | length 201.9
  TOP w6.16: U16.26@3340.16,1975.96 3370,1946.13 3370,1850 3350,1830 R102.2@3350,1794.68
N15599792: R90.2 R91.1 R93.1 R94.1 R95.1 | length 281
  TOP w10: R94.1@3270,1655.32 R93.1@3310,1655.32 3310,1625 3331,1604 3374,1604 3390,1620 R95.1@3390,1655.32 R91.1@3430,1655.32 R90.2@3470,1655.32
N15600759: R106.2 R107.1 R108.1 R109.1 | length 140.6
  TOP w10: R107.1@3150,1694.68 R106.2@3110,1694.68 R108.1@3110,1755.32 R109.1@3150,1755.32
N15600826: R110.2 R111.2 U16.31 | length 339.5
  TOP w6.16: U16.31@3384.71,2059.49 3390.22,2065 3565,2065 3605,2025 R110.2@3605,1964.68 R111.2@3565,1964.68
N15601838: C81.1 U16.37 Y1.1 | length 283
  TOP w6.16: U16.37@3317.9,2126.3 3365,2173.4 3365,2259.68 C81.1@3354.68,2270 3375,2290.32 3375,2334.31 3368.84,2340.47 Y1.1@3334.72,2340.47
N15601846: C82.1 U16.36 Y1.3 | length 336.2
  TOP w6.16: U16.36@3329.03,2115.16 3382.81,2168.94 3382.81,2252.49 C82.1@3400.32,2270 3390,2280.32 3390,2370.16 3419.37,2399.53 Y1.3@3425.28,2399.53
N15602173: D28.2 R119.2 R120.2 U16.12 | length 683.9
  TOP w8: v1(3110,2005) 3120,1995 3142.05,1995 U16.12@3156.43,2009.37
  BOTTOM w6.16: D28.2@2632.95,2110 2687.63,2164.68 R120.2@2690,2164.68 R119.2@2730,2164.68 3055.32,2164.68 3075,2145 3075,2040 v1(3110,2005)
N15602572: R118.1 U16.32 | length 366.7
  TOP w6.16: U16.32@3373.57,2070.63 3387.95,2085 3585,2085 3655,2015 R118.1@3655,1964.68
N15602600: R117.2 R121.2 R122.1 | length 96.3
  BOTTOM w10: R122.1@3470,2054.68 3509.36,2015.32 R121.2@3510,2015.32 R117.2@3550,2015.32
N15603170: C83.1 J17.1 | length 127.9
  BOTTOM w25: C83.1@3208,2399.68 3208.13,2399.81 J17.1@3208.13,2527.52
N15605512: R98.1 U16.39 | length 152.6
  TOP w6.16: R98.1@3260,2270.32 3315,2215.32 3315,2167.95 U16.39@3295.63,2148.57
N15605755: C77.1 C78.1 R89.1 R92.1 U16.28 | length 96.1
  TOP w8: U16.28@3362.44,1998.24 3385.34,1975.34
  TOP w12: 3385.34,1975.34 v1(3405.34,1955.34)
  TOP w20: v1(3405,1920) 3405,1955 v1(3405.34,1955.34)
N15611443: C116.1 R140.2 U21.4 | length 94.9
  BOTTOM w6.16: R140.2@4305,3099.68 C116.1@4345,3099.68 4370.32,3099.68 4375.79,3094.21 U21.4@4397.6,3094.21
N15611553: R143.1 U21.3 | length 59
  BOTTOM w10: R143.1@4345,2980.32 4360.17,2980.32 4375.64,2995.79 U21.3@4397.6,2995.79
N15653247: C122.1 R149.2 U24.4 | length 94.9
  BOTTOM w6.16: R149.2@935.32,2260 C122.1@935.32,2300 935.32,2327.25 940.79,2332.72 U24.4@940.79,2352.6
N15653357: R152.1 U24.3 | length 66.9
  BOTTOM w6.16: U24.3@1039.21,2352.6 1049.21,2352.6 1059.68,2342.13 R152.1@1059.68,2300
N15653957: C119.1 R146.2 U23.4 | length 94.9
  BOTTOM w6.16: R146.2@3555.39,3099.92 C119.1@3595.39,3099.92 3620.08,3099.92 3625.55,3094.45 U23.4@3647.99,3094.45
N15654067: R147.1 U23.3 | length 59
  BOTTOM w10: R147.1@3595.39,2980.56 3610.56,2980.56 3626.03,2996.03 U23.3@3647.99,2996.03
N15659726: C18.2 R7.2 R8.1 U3.5 | length 185.5
  BOTTOM w10: U3.5@192.76,2015 202.41,2015 240,1977.41 C18.2@240,1934.68 ; R8.1@200,1934.68 C18.2@240,1934.68 ; R7.2@280,1934.68 C18.2@240,1934.68
N15752445: L9.1 U25.G1 U25.G2 U25.G3 U25.G4 | length 1481.5
  TOP w30: L9.1@2166.5,2375 2256.9,2375 2286.9,2405 U25.G1@2286.9,2445 U25.G2@2286.9,2819.02 2286.9,3020 2316.9,3050 2512.81,3050 2542.81,3020 U25.G4@2542.81,2921.39
  BOTTOM w30: U25.G3@2542.81,2567.05 U25.G4@2542.81,2921.39
N15772454: J22.14 R161.2 | length 146.2
  TOP w6.16: R161.2@4989.68,1640 5010.79,1640 5055.31,1595.48 J22.14@5117.47,1595.48
N15774097: J21.14 R160.2 | length 234.2
  TOP w6.16: R160.2@4889.68,2450 5005,2450 5020.48,2465.48 J21.14@5117.47,2465.48
N15830872: C176.2 D43.2 J28.3 J28.5 | length 649.4
  TOP w8: v1(1501.8,2499.68) 1545.56,2499.68 C176.2@1550,2495.24
  BOTTOM w8: v1(1501.8,2499.68) D43.2@1475,2499.68 1410,2564.68 1410,2835 1436.24,2861.24 J28.5@1501.39,2861.24 1572.25,2790.38 J28.3@1580.13,2790.38
N15830941: C175.2 D42.2 J28.2 R215.2 | length 739
  TOP w8: C175.2@1270,2495.24 1274.44,2499.68 v1(1313.2,2499.68)
  BOTTOM w8: v1(1313.2,2499.68) R215.2@1340,2499.68 D42.2@1380,2499.68 1382,2501.68 1382,2872 1516.91,3006.91 J28.2@1580.13,3006.91
N15838979: J28.4 R214.2 | length 332.1
  TOP w10: J28.4@1501.39,2628.96 1681.04,2628.96 1725,2585 R214.2@1725,2494.68
N15851038: C171.1 R212.2 R213.1 | length 138.9
  TOP w10: R212.2@1765,2310.32 C171.1@1805,2310.32 1805,2265 1825,2245 R213.1@1850.32,2245
N15980269: J13.2 R73.2 | length 228.4
  TOP w10: R73.2@2590,346.5 2608.5,365 2740,365 J13.2@2790,315
N16735828: LED2.1 R45.1 | length 70
  TOP w6.16: LED2.1@5040,325.32 R45.1@5040,395.32
N16735933: LED3.1 R48.1 | length 70
  TOP w6.16: LED3.1@4915,325.32 R48.1@4915,395.32
N16793147: D15.2 J12.1 R60.2 | length 291.8
  BOTTOM w6.16: R60.2@4579.68,630 4604.68,605 4659.68,605 D15.2@4684.68,630 4715,630 4783.58,561.42 J12.1@4822.41,561.42
N16793149: D19.2 J12.7 R64.2 | length 283.6
  BOTTOM w6.16: R64.2@4579.68,875 4598.76,855.92 4602.18,852.5 4662.18,852.5 D19.2@4684.68,875 4700,875 4753.74,821.26 J12.7@4822.41,821.26
N16793151: D18.2 J12.5 R63.2 | length 313.8
  BOTTOM w6.16: R63.2@4579.68,830 4607.18,802.5 4657.18,802.5 D18.2@4684.68,830 4705,830 4730,805 4730,790 4785.35,734.65 J12.5@4822.41,734.65
N16793153: D17.2 J12.3 R62.2 | length 291.2
  BOTTOM w6.16: R62.2@4579.68,720 4602.19,697.5 4662.18,697.5 D17.2@4684.68,720 4705,720 4776.97,648.03 J12.3@4822.41,648.03
N16793155: D16.2 J12.2 R61.2 | length 290.5
  BOTTOM w6.16: R61.2@4579.68,675 4602.19,652.5 4662.18,652.5 D16.2@4684.68,675 4705,675 4775.27,604.73 J12.2@4822.41,604.73
N16793157: D20.2 J12.8 R65.2 | length 284.3
  BOTTOM w6.16: R65.2@4579.68,920 4598.76,900.92 4602.18,897.5 4662.18,897.5 D20.2@4684.68,920 4705,920 4760.43,864.57 J12.8@4822.41,864.57
N16793300: D21.2 J12.9 R66.2 | length 285
  BOTTOM w6.16: R66.2@4579.68,965 4598.76,945.92 4602.18,942.5 4662.18,942.5 D21.2@4684.68,965 4702.36,965 4759.48,907.88 J12.9@4822.41,907.88
N16795570: LED4.1 R49.1 | length 70
  TOP w6.16: LED4.1@4790,325.32 R49.1@4790,395.32
N16795883: C37.2 R23.2 R24.2 R25.1 U5.5 | length 218.5
  BOTTOM w10: R24.2@180,2404.68 C37.2@220,2404.68 ; U5.5@192.76,2485 202.41,2485 221.47,2465.93 221.47,2429.26 220,2427.79 C37.2@220,2404.68 ; R23.2@300,2404.68 R25.1@260,2404.68 C37.2@220,2404.68
N16811933: J27.1 R205.2 R206.2 | length 275.4
  TOP w6.16: v1(4430,2418.78) 4553.78,2418.78 4566.98,2431.98 J27.1@4566.98,2490.88
  BOTTOM w6.16: R205.2@4390,2384.68 R206.2@4430,2384.68 v1(4430,2418.78)
N16823854: J27.7 R207.2 | length 222.2
  TOP w6.16: J27.7@4472.49,2490.88 4472.49,2537.49 4480,2545 v1(4480,2545.25)
  BOTTOM w6.16: R207.2@4470,2384.68 4470,2535 4480,2545 v1(4480,2545.25)
N16928945: J27.20 R208.1 | length 99.8
  TOP w6.16: J27.20@4141.79,2168.04 v1(4141.79,2225)
  BOTTOM w6.16: v1(4141.79,2225) 4160,2206.79 R208.1@4160,2189.68
N16929135: J27.22 R209.1 | length 96.3
  TOP w6.16: J27.22@4110.29,2168.04 v1(4110.29,2225)
  BOTTOM w6.16: v1(4110.29,2225) 4120,2215.29 R209.1@4120,2189.68
N16980859: C164.1 R199.2 U36.2 U37.6 | length 384.7
  BOTTOM w6.16: R199.2@4579.68,1200 C164.1@4579.68,1240 4598.84,1240 4605,1246.16 4605,1295.2 4621.16,1311.36 4676.36,1311.36 4689.69,1324.68 U37.6@4689.69,1346.58 4689.69,1359.68 4700.16,1370.16 U36.2@4821.24,1370.16
N16980861: C163.1 R200.2 U36.3 U37.4 | length 383.4
  BOTTOM w6.16: R200.2@4579.68,1440 C163.1@4579.68,1400 4633.1,1346.58 U37.4@4650.31,1346.58 4650.31,1395.32 4675,1420 4740,1420 4790.16,1470.16 U36.3@4821.24,1470.16
N16980863: C162.1 R198.2 R202.2 U36.7 U37.5 | length 401.2
  BOTTOM w6.16: R198.2@4579.68,1280 R202.2@4579.68,1320 C162.1@4579.68,1360 4614.68,1325 4663.84,1325 4670,1331.16 U37.5@4670,1346.58 4670,1375 4690,1395 4754.84,1395 4780,1420.16 U36.7@4821.24,1420.16
N17405290: C29.2 R20.2 R22.1 U5.4 | length 149.2
  BOTTOM w6.16: R20.2@124.68,2525 C29.2@124.68,2485 R22.1@124.68,2445 190.16,2445 U5.4@192.76,2447.6
N17423559: C19.1 U4.6 | length 50.7
  BOTTOM w20: C19.1@185.32,1630 192.76,1622.56 U4.6@192.76,1582.4
N17423580: C19.2 L2.1 U4.2
N17423608: C27.2 R14.2 R15.1 U4.5 | length 178.5
  BOTTOM w10: U4.5@192.76,1545 202.41,1545 221.47,1525.93 221.47,1489.26 220,1487.79 C27.2@220,1464.68 R15.1@260,1464.68 R14.2@300,1464.68
N17423737: C20.2 R11.2 R13.1 U4.4 | length 150.3
  BOTTOM w10: R11.2@129.68,1605 C20.2@129.68,1565 R13.1@129.68,1525 147.08,1507.6 U4.4@192.76,1507.6
N17430242: R33.1 U7.3 | length 59.7
  BOTTOM w6.16: U7.3@442.4,1134.21 470.79,1134.21 475,1130 R33.1@500.32,1130
N17430314: C44.1 R32.2 U7.4 | length 99.5
  BOTTOM w6.16: U7.4@442.4,1035.79 495.47,1035.79 C44.1@500,1040.32 R32.2@540,1040.32
N17443353: R31.1 U6.3 | length 59.7
  BOTTOM w6.16: U6.3@442.4,954.21 465.79,954.21 470,950 R31.1@500.32,950
N17443371: C41.1 R30.2 U6.4 | length 99.5
  BOTTOM w6.16: U6.4@442.4,855.79 495.47,855.79 C41.1@500,860.32 R30.2@540,860.32
N17444423: C38.2 Q5.1 Q6.3 R27.2 | length 278.9
  BOTTOM w6.16: Q5.1@444,1307.5 480.32,1343.82 C38.2@480.32,1380 R27.2@480.32,1420 480.32,1422.74 507.58,1450 554,1450 Q6.3@599,1405
N17444523: Q6.1 R28.2 R29.1 | length 216.8
  BOTTOM w6.16: R28.2@620.32,1250 R29.1@620.32,1295 620.32,1350.32 640,1370 640,1403.5 Q6.1@679,1442.5
N17454508: C69.2 U13.1 | length 92.7
  BOTTOM w12: U13.1@995.2,1379.8 995.2,1429.88 C69.2@1025.32,1460
N17454513: C69.1 U13.3 | length 92.8
  BOTTOM w12: C69.1@1064.68,1460 1095.2,1429.48 U13.3@1095.2,1379.8
N17455367: C70.2 U13.4 | length 80.4
  BOTTOM w12: U13.4@1144.8,1379.8 1145.32,1380.32 C70.2@1145.32,1460
N17455372: C70.1 U13.5 | length 84.6
  BOTTOM w12: C70.1@1184.68,1460 1195.2,1449.48 U13.5@1195.2,1379.8
N17455499: C68.1 U13.6 | length 90.8
  BOTTOM w12: U13.6@1244.8,1379.8 1244.8,1434.48 C68.1@1270.32,1460
N17455508: C66.1 U13.2 | length 164.9
  BOTTOM w12: C66.1@940,1334.68 954.68,1320 1035,1320 1044.8,1329.8 U13.2@1044.8,1379.8
N17466585: L4.1 U16.30
N17592125: C154.1 U35.6 | length 53.6
  BOTTOM w20: C154.1@4345.32,1795 4347.76,1792.56 U35.6@4347.76,1742.4
N17592129: C154.2 L10.1 U35.2
N17592172: C155.2 R201.2 R203.1 U35.4 | length 138.2
  BOTTOM w8: R201.2@4294.68,1760 C155.2@4294.68,1720 R203.1@4294.68,1680 4307.08,1667.6 U35.4@4347.76,1667.6
N17592220: R204.2 U35.5 | length 158.7
  BOTTOM w6.16: R204.2@4294.68,1640 4364.5,1640 4380,1655.5 4380,1679.69 4354.69,1705 U35.5@4347.76,1705
N17633217: C117.1 U22.3 Y2.1 | length 212.9
  TOP w6.16: U22.3@4094.84,1817.68 4094.84,1884.52 C117.1@4105.32,1895 4095.61,1904.71 4095.61,1975.61 4124.53,2004.53 Y2.1@4130.28,2004.53
N17633237: C118.2 U22.4 Y2.3 | length 171.9
  TOP w6.16: Y2.3@4039.72,1945.47 4068.37,1945.47 4080,1933.84 4080,1910.32 C118.2@4064.68,1895 4075.16,1884.52 U22.4@4075.16,1817.68
N17633305: R144.2 U22.16 | length 82.7
  TOP w6.16: v1(4094.84,1600) U22.16@4094.84,1652.32
  BOTTOM w6.16: v1(4094.84,1600) 4095,1600.16 R144.2@4095,1630.32
N17633317: R145.2 U22.18 | length 83
  TOP w6.16: v1(4134.21,1600) U22.18@4134.21,1652.32
  BOTTOM w6.16: v1(4134.21,1600) 4135,1600.79 R145.2@4135,1630.32
N17685591: C151.2 Q12.1 Q13.3 R195.2 | length 475.4
  TOP w6.16: Q12.1@4812.5,996 4693.16,996 4680,982.84 4680,893.48 4693.16,880.32 R195.2@4720,880.32 C151.2@4760,880.32 4760,855 4770,845 4840,845 4850,835 Q13.3@4850,796
N17685601: Q13.1 R196.2 R197.1 | length 100.5
  TOP w6.16: R196.2@4720,735.32 R197.1@4760,735.32 4779.32,716 Q13.1@4812.5,716
N17685851: Q12.2 R193.2
N17690217: R194.1 U34.3 | length 59.8
  BOTTOM w10: R194.1@4579.68,1020 4609.21,1049.53 U34.3@4609.21,1067.6
N17690290: C148.1 R192.2 U34.4 | length 108.1
  BOTTOM w6.16: R192.2@4410,1085.32 C148.1@4450,1085.32 4467.72,1067.6 U34.4@4510.79,1067.6
N17695706: C133.1 R171.2 U28.4 U30.4 | length 346.4
  TOP w6.16: R171.2@4760,1954.68 C133.1@4760,2000.32 ; U28.4@4812.6,1970.79 4812.6,1977.4 4789.68,2000.32 C133.1@4760,2000.32 ; U30.4@4812.6,2150.79 4745.79,2150.79 4735,2140 4735,2025.32 C133.1@4760,2000.32
N17695791: R174.1 U30.3 | length 64.8
  TOP w15: R174.1@4760,2219.68 4789.53,2249.21 U30.3@4812.6,2249.21
N17695827: R173.1 U28.3 | length 59.3
  TOP w15: R173.1@4760,2085.32 4776.11,2069.21 U28.3@4812.6,2069.21
N17697466: J17.13 R114.1 | length 154.5
  BOTTOM w15: J17.13@2822.1,3070.44 2862.22,3030.32 R114.1@2960,3030.32
N17697880: R181.1 U32.3 | length 53.8
  BOTTOM w10: R181.1@4865,2119.68 4865,2135 4879.21,2149.21 U32.3@4879.21,2167.6
N17697953: C140.1 R179.2 U32.4 | length 127.7
  BOTTOM w6.16: U32.4@4780.79,2167.6 4817.4,2167.6 4825,2160 C140.1@4825,2119.68 R179.2@4785,2119.68
N17701231: J14.2 R74.2 | length 108
  TOP w10: J14.2@2430,315 2493.5,315 R74.2@2525,346.5
N17702194: J15.3 R81.2 | length 207.5
  BOTTOM w10: R81.2@1690,181.5 1670,201.5 1670,310 1680,320 1736.06,320 J15.3@1736.41,319.64
N17702199: J15.4 R82.2 | length 204.2
  BOTTOM w10: J15.4@1586.41,319.64 1640,319.64 1650,309.64 1650,201.5 R82.2@1630,181.5
N17702222: J15.2 R80.2 | length 204.2
  BOTTOM w10: J15.2@1886.41,319.64 1940,319.64 1950,309.64 1950,201.5 R80.2@1930,181.5
N17702231: J15.1 R79.2 | length 212.6
  BOTTOM w10: R79.2@1990,181.5 1966,205.5 1966,309.64 1976,319.64 J15.1@2036.41,319.64
N17728858: D22.1 R71.1 | length 146.9
  BOTTOM w10: R71.1@2119.68,1105 2155,1105 2190,1140 D22.1@2190,1202.05
N17729021: D23.1 R72.1 | length 149.2
  BOTTOM w10: R72.1@1789.68,1105 1829,1105 1860,1136 D23.1@1860,1202.05
N17731599: J11.6 R59.2 | length 622.8
  BOTTOM w12: J11.6@491.14,319.64 581.5,410 760,410 855,505 855,623.5 R59.2@900,668.5
N17731608: J11.4 R58.2 | length 750.3
  BOTTOM w12: J11.4@791.14,319.64 872.5,401 1162,401 1183,422 1183,642 1151.5,673.5 R58.2@1100,673.5
N17731627: J11.1 R56.2 | length 503.2
  BOTTOM w12: J11.1@1241.14,319.64 1369.64,319.64 1395,345 1395,648.5 R56.2@1420,673.5
N17748815: Q5.2 R26.2 | length 83.5
  BOTTOM w25: Q5.2@444,1232.5 450,1238.5 R26.2@525,1238.5
N17750545: Q1.1 Q2.3 R12.2 | length 125.5
  TOP w6.16: Q2.3@906.5,2390 926.18,2409.68 R12.2@965,2409.68 982.82,2427.5 Q1.1@1016.5,2427.5
N17750554: D2.1 J2.1 Q1.3 | length 347.2
  TOP w20: J2.1@949.53,2639.41 996.93,2592.01 D2.1@996.93,2500 1060,2500 1096.5,2463.5 Q1.3@1096.5,2390
N17750632: Q2.1 R17.2 R18.1 | length 205.7
  TOP w6.16: Q2.1@826.5,2427.5 860,2394 860,2310.32 R18.1@849.68,2300 R17.2@849.68,2240
N17759502: C65.1 D9.3 U12.8 | length 428.5
  TOP w15: v1(719.68,2270) C65.1@719.68,2300 719.68,2334.68 736,2351 D9.3@736,2390
  BOTTOM w15: U12.8@587.95,2475 660,2475 719.68,2415.32 v1(719.68,2270)
N17770939: R141.1 U22.15 | length 212.2
  TOP w6.23: R141.1@3929.68,1565 3939.68,1575 4050,1575 4070,1595 4070,1620 4075.16,1625.16 U22.15@4075.16,1652.32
